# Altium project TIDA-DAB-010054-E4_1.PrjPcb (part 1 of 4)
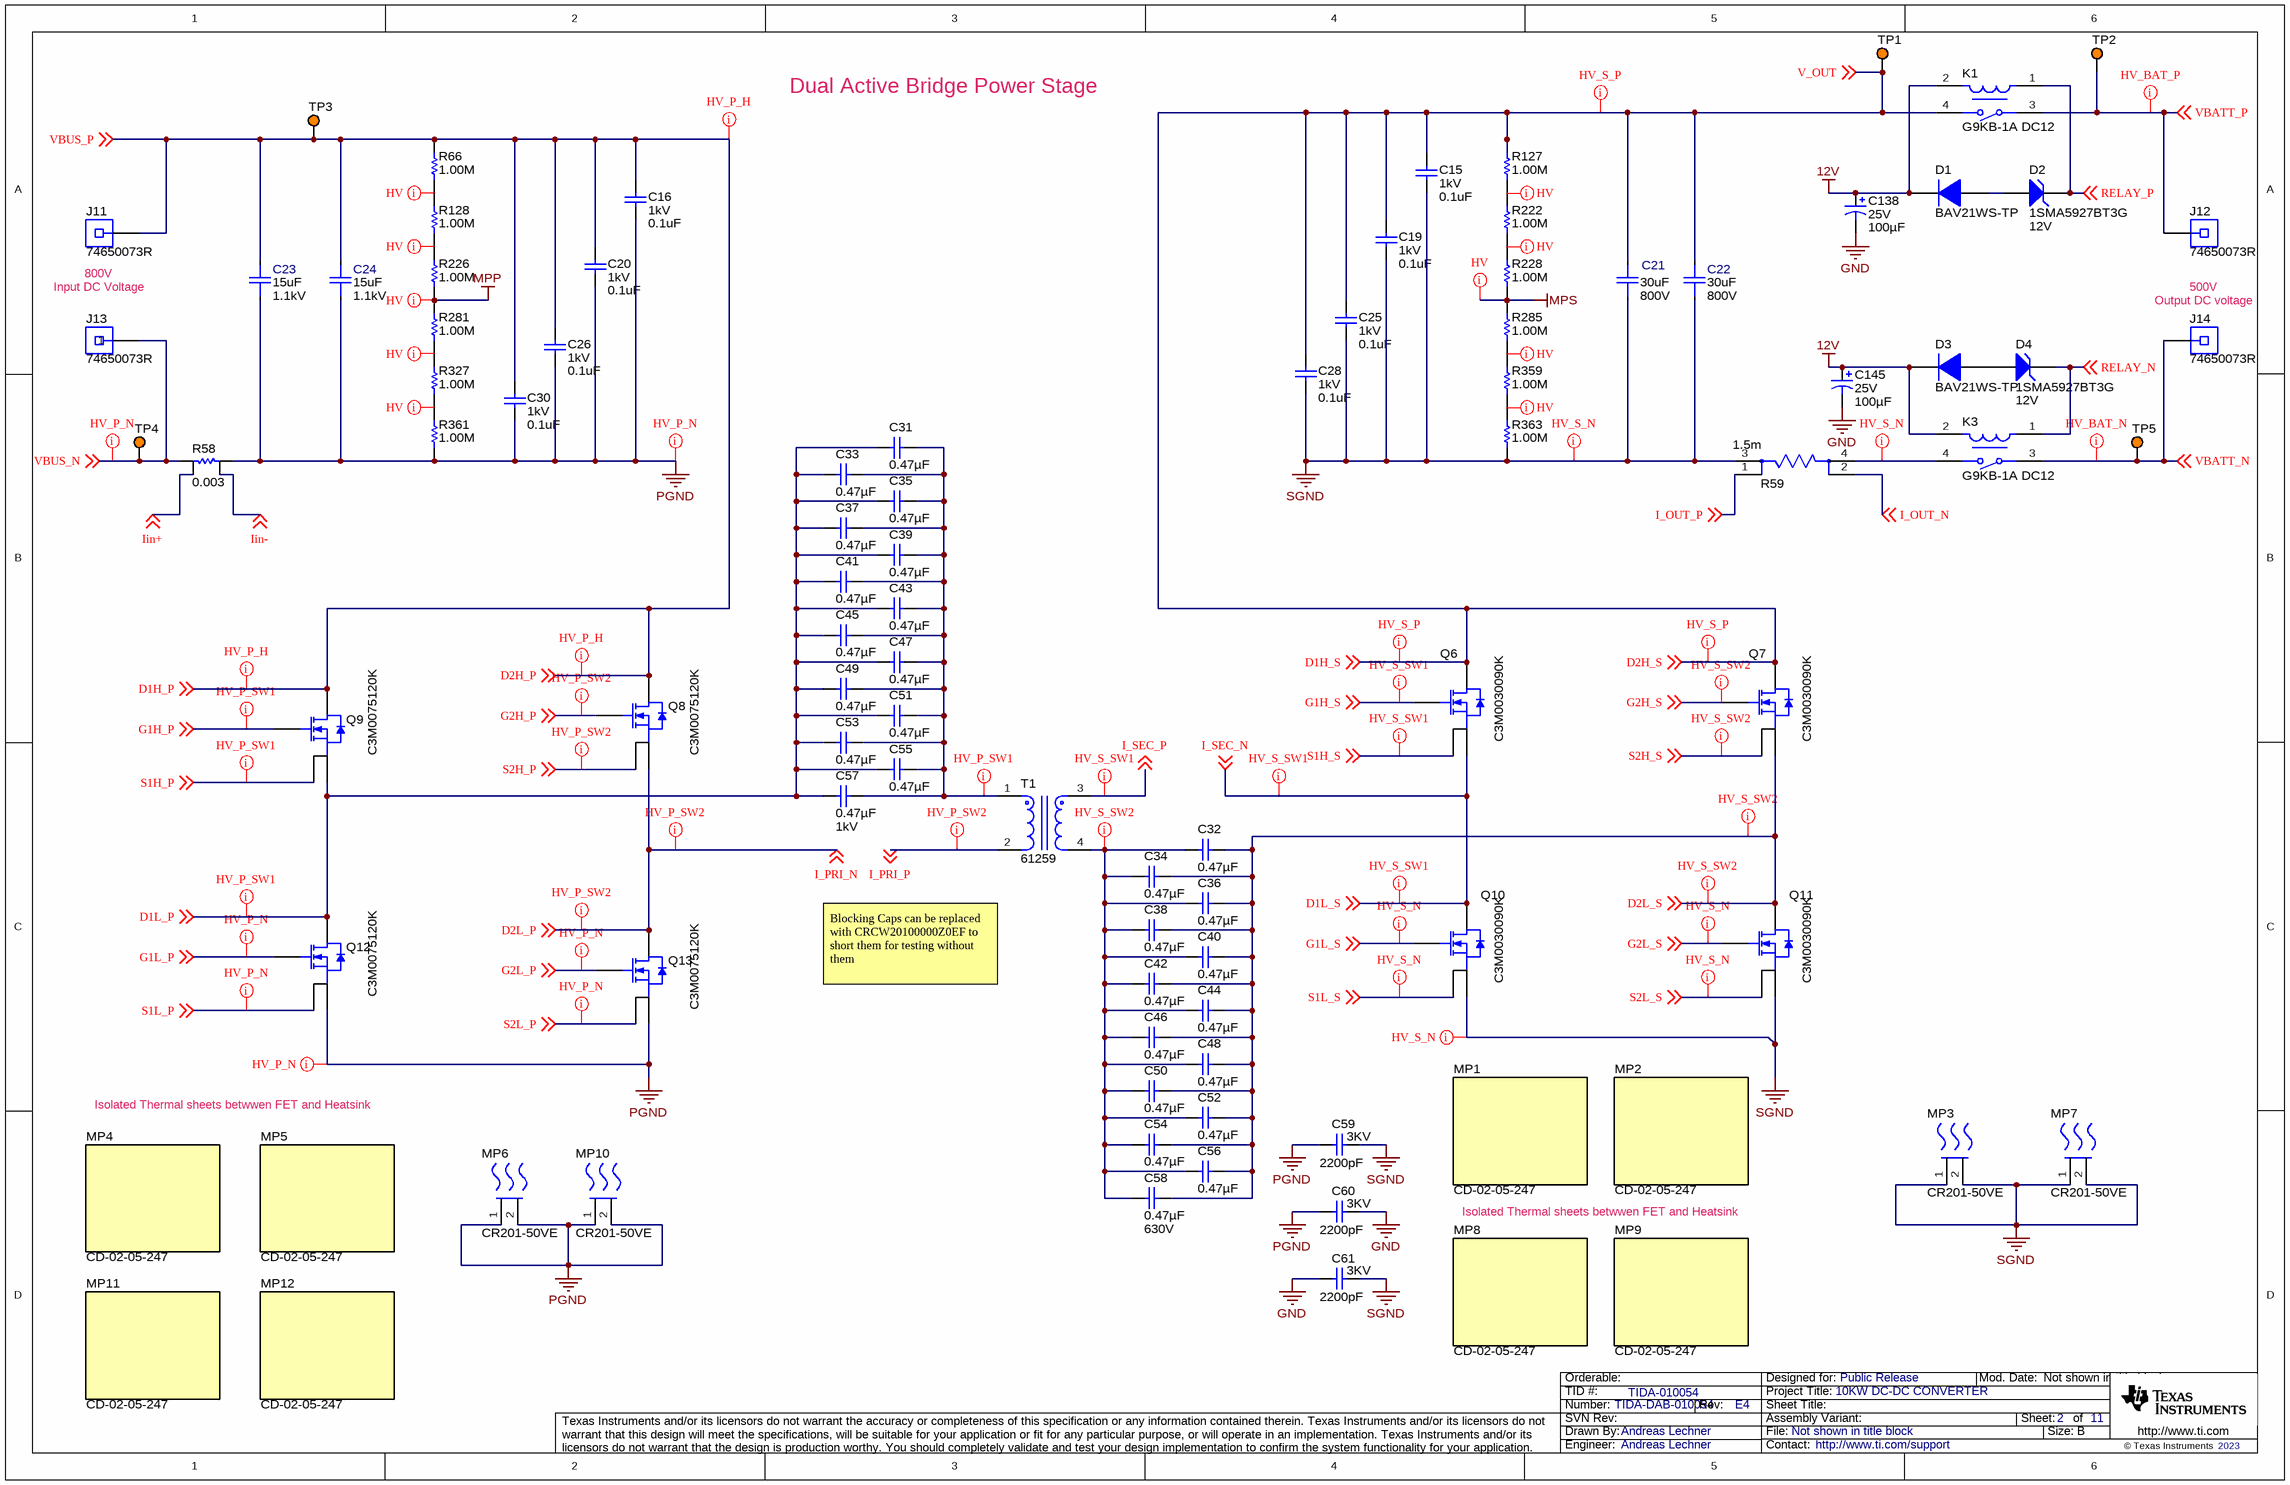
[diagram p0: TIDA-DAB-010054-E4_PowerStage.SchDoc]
CopyrightYear: 2023; DrawnBy: Andreas Lechner; PCB_Layout: Andreas Lechner; PCB_Rev: E4; PRJ_Customer: Public Release; PRJ_Engineer: Andreas Lechner; PRJ_Number: TIDA-DAB-010054; PRJ_Title: 10KW DC-DC CONVERTER; SCH_Rev: E4; TechSupport: http://www.ti.com/support; TID: TIDA-010054
11 sheets, 874 parts. Net scope: global (net labels, ports and power ports of the same name join across sheets).
Board file: TIDA-DAB-010054-E4.PcbDoc
Sheets:
  TIDA-DAB-010054-E4_Block Diagram.SchDoc
  TIDA-DAB-010054-E4_PowerStage.SchDoc
  TIDA-DAB-010054-E4_PrimarySideSensing.SchDoc
  TIDA-DAB-010054-E4_SecondarySideSensing.SchDoc
  TIDA-DAB-010054-E4_GateDriverPrimHB1.SchDoc
  TIDA-DAB-010054-E4_GateDriverPrimHB2.SchDoc
  TIDA-DAB-010054-E4_GateDriverSecHB1.SchDoc
  TIDA-DAB-010054-E4_GateDriverSecHB2.SchDoc
  TIDA-DAB-010054-E4_Power Tree.SchDoc
  TIDA-DAB-010054-E4_Control Card.SchDoc
  TIDA-DAB-010054-E4_EVM_Hardware.SchDoc

## Sheet TIDA-DAB-010054-E4_Block Diagram.SchDoc
size 431 x 279 mm; Date: Not shown in title block; ApprovedBy: Not shown in title block; CheckedBy: Not shown in title block; Author: Not shown in title block; CompanyName: Not shown in title block; Engineer: Not shown in title block; Organization: Not shown in title block; Address1: Not shown in title block; Address2: Not shown in title block; Address3: Not shown in title block; Address4: Not shown in title block; DocumentNumber: 1; Revision: Use project parameter SCH_Rev; SheetNumber: 1; SheetTotal: 11; PageSetup: Record=PageOptions¦CenterHorizontal=True¦CenterVertical=True¦PrintScale=1.00¦XCorrection=1.00¦YCorrection=1.00¦PrintKind=0¦BorderSize=5000000¦LeftOffset=0¦BottomOffset=0¦Orientation=2¦PaperLength=1000¦PaperWidth=1000¦Scale=100¦PaperSource=15¦PrintQuality=600¦MediaType=1¦DitherType=10¦PaperKind=Letter¦PrintScaleMode=1

## Sheet TIDA-DAB-010054-E4_PowerStage.SchDoc
size 431 x 279 mm; Date: Not shown in title block; ApprovedBy: Not shown in title block; CheckedBy: Not shown in title block; Author: Not shown in title block; CompanyName: Not shown in title block; Engineer: Not shown in title block; Organization: Not shown in title block; Address1: Not shown in title block; Address2: Not shown in title block; Address3: Not shown in title block; Address4: Not shown in title block; DocumentNumber: 1; Revision: Use project parameter SCH_Rev; SheetNumber: 2; SheetTotal: 11; PageSetup: Record=PageOptions¦CenterHorizontal=True¦CenterVertical=True¦PrintScale=1.00¦XCorrection=1.00¦YCorrection=1.00¦PrintKind=0¦BorderSize=5000000¦LeftOffset=0¦BottomOffset=0¦Orientation=2¦PaperLength=1000¦PaperWidth=1000¦Scale=100¦PaperSource=15¦PrintQuality=600¦MediaType=1¦DitherType=10¦PaperKind=Letter¦PrintScaleMode=1

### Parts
C15  VDC_V: 1kV  ValueDisplayed: 0.1uF  [1812_254]  (hidden comment: C1812V104KDRACTU)
C16  VDC_V: 1kV  ValueDisplayed: 0.1uF  [1812_254]  (hidden comment: C1812V104KDRACTU)
C19  VDC_V: 1kV  ValueDisplayed: 0.1uF  [1812_254]  (hidden comment: C1812V104KDRACTU)
C20  VDC_V: 1kV  ValueDisplayed: 0.1uF  [1812_254]  (hidden comment: C1812V104KDRACTU)
C21  ValueDisplayed: 30uF  VDC_V: 800V  [FP-B32716H8306K000_RADIAL-MFG]  (hidden comment: B32716H8306K000)
C22  ValueDisplayed: 30uF  VDC_V: 800V  [FP-B32716H8306K000_RADIAL-MFG]  (hidden comment: B32716H8306K000)
C23  ValueDisplayed: 15uF  VDC_V: 1.1kV  [FP-B32716H1156K000_RADIAL-MFG]  (hidden comment: B32716H1156K000)
C24  ValueDisplayed: 15uF  VDC_V: 1.1kV  [FP-B32716H1156K000_RADIAL-MFG]  (hidden comment: B32716H1156K000)
C25  VDC_V: 1kV  ValueDisplayed: 0.1uF  [1812_254]  (hidden comment: C1812V104KDRACTU)
C26  VDC_V: 1kV  ValueDisplayed: 0.1uF  [1812_254]  (hidden comment: C1812V104KDRACTU)
C28  VDC_V: 1kV  ValueDisplayed: 0.1uF  [1812_254]  (hidden comment: C1812V104KDRACTU)
C30  VDC_V: 1kV  ValueDisplayed: 0.1uF  [1812_254]  (hidden comment: C1812V104KDRACTU)
C31  ValueDisplayed: 0.47µF  [2220]  (hidden comment: 2220Y1K00474KETWS2)
C32  ValueDisplayed: 0.47µF  [2220_280]  (hidden comment: CGA9P1X7T2J474M250KC)
C33  ValueDisplayed: 0.47µF  [2220]  (hidden comment: 2220Y1K00474KETWS2)
C34  ValueDisplayed: 0.47µF  [2220_280]  (hidden comment: CGA9P1X7T2J474M250KC)
C35  ValueDisplayed: 0.47µF  [2220]  (hidden comment: 2220Y1K00474KETWS2)
C36  ValueDisplayed: 0.47µF  [2220_280]  (hidden comment: CGA9P1X7T2J474M250KC)
C37  ValueDisplayed: 0.47µF  [2220]  (hidden comment: 2220Y1K00474KETWS2)
C38  ValueDisplayed: 0.47µF  [2220_280]  (hidden comment: CGA9P1X7T2J474M250KC)
C39  ValueDisplayed: 0.47µF  [2220]  (hidden comment: 2220Y1K00474KETWS2)
C40  ValueDisplayed: 0.47µF  [2220_280]  (hidden comment: CGA9P1X7T2J474M250KC)
C41  ValueDisplayed: 0.47µF  [2220]  (hidden comment: 2220Y1K00474KETWS2)
C42  ValueDisplayed: 0.47µF  [2220_280]  (hidden comment: CGA9P1X7T2J474M250KC)
C43  ValueDisplayed: 0.47µF  [2220]  (hidden comment: 2220Y1K00474KETWS2)
C44  ValueDisplayed: 0.47µF  [2220_280]  (hidden comment: CGA9P1X7T2J474M250KC)
C45  ValueDisplayed: 0.47µF  [2220]  (hidden comment: 2220Y1K00474KETWS2)
C46  ValueDisplayed: 0.47µF  [2220_280]  (hidden comment: CGA9P1X7T2J474M250KC)
C47  ValueDisplayed: 0.47µF  [2220]  (hidden comment: 2220Y1K00474KETWS2)
C48  ValueDisplayed: 0.47µF  [2220_280]  (hidden comment: CGA9P1X7T2J474M250KC)
C49  ValueDisplayed: 0.47µF  [2220]  (hidden comment: 2220Y1K00474KETWS2)
C50  ValueDisplayed: 0.47µF  [2220_280]  (hidden comment: CGA9P1X7T2J474M250KC)
C51  ValueDisplayed: 0.47µF  [2220]  (hidden comment: 2220Y1K00474KETWS2)
C52  ValueDisplayed: 0.47µF  [2220_280]  (hidden comment: CGA9P1X7T2J474M250KC)
C53  ValueDisplayed: 0.47µF  [2220]  (hidden comment: 2220Y1K00474KETWS2)
C54  ValueDisplayed: 0.47µF  [2220_280]  (hidden comment: CGA9P1X7T2J474M250KC)
C55  ValueDisplayed: 0.47µF  [2220]  (hidden comment: 2220Y1K00474KETWS2)
C56  ValueDisplayed: 0.47µF  [2220_280]  (hidden comment: CGA9P1X7T2J474M250KC)
C57  ValueDisplayed: 0.47µF  VDC_V: 1kV  [2220]  (hidden comment: 2220Y1K00474KETWS2)
C58  ValueDisplayed: 0.47µF  VDC_V: 630V  [2220_280]  (hidden comment: CGA9P1X7T2J474M250KC)
C59  VDC_V: 3KV  ValueDisplayed: 2200pF  [CAPRD1000W60D900H1200]  (hidden comment: CK45-B3FD222KYVNA)
C60  VDC_V: 3KV  ValueDisplayed: 2200pF  [CAPRD1000W60D900H1200]  (hidden comment: CK45-B3FD222KYVNA)
C61  VDC_V: 3KV  ValueDisplayed: 2200pF  [CAPRD1000W60D900H1200]  (hidden comment: CK45-B3FD222KYVNA)
C138  VDC_V: 25V  ValueDisplayed: 100µF  [UWT_630x770]  (hidden comment: UWT1E101MCL1GS)
C145  VDC_V: 25V  ValueDisplayed: 100µF  [UWT_630x770]  (hidden comment: UWT1E101MCL1GS)
D1  BAV21WS-TP  [SOD-323]
D2  1SMA5927BT3G  value 12V  [SMA]
D3  BAV21WS-TP  [SOD-323]
D4  1SMA5927BT3G  value 12V  [SMA]
J11  74650073R  [Wurth_WP-THRBU]
J12  74650073R  [Wurth_WP-THRBU]
J13  74650073R  [Wurth_WP-THRBU]
J14  74650073R  [Wurth_WP-THRBU]
K1  G9KB-1A DC12  [FP-G9KB-1A DC12_PTH_RELAY_50MM0_36MM7-MFG]
K3  G9KB-1A DC12  [FP-G9KB-1A DC12_PTH_RELAY_50MM0_36MM7-MFG]
MP1  CD-02-05-247  [FP-CD-02-05-247_THERM_PAD_24MM13_19MM05-MFG]
MP2  CD-02-05-247  [FP-CD-02-05-247_THERM_PAD_24MM13_19MM05-MFG]
MP3  CR201-50VE  [FP-CR201-50VE_PTH_HEATSINKS_34MM0_50MM0-MFG]
MP4  CD-02-05-247  [FP-CD-02-05-247_THERM_PAD_24MM13_19MM05-MFG]
MP5  CD-02-05-247  [FP-CD-02-05-247_THERM_PAD_24MM13_19MM05-MFG]
MP6  CR201-50VE  [FP-CR201-50VE_PTH_HEATSINKS_34MM0_50MM0-MFG]
MP7  CR201-50VE  [FP-CR201-50VE_PTH_HEATSINKS_34MM0_50MM0-MFG]
MP8  CD-02-05-247  [FP-CD-02-05-247_THERM_PAD_24MM13_19MM05-MFG]
MP9  CD-02-05-247  [FP-CD-02-05-247_THERM_PAD_24MM13_19MM05-MFG]
MP10  CR201-50VE  [FP-CR201-50VE_PTH_HEATSINKS_34MM0_50MM0-MFG]
MP11  CD-02-05-247  [FP-CD-02-05-247_THERM_PAD_24MM13_19MM05-MFG]
MP12  CD-02-05-247  [FP-CD-02-05-247_THERM_PAD_24MM13_19MM05-MFG]
Q6  C3M0030090K  [TO-247-4]
Q7  C3M0030090K  [TO-247-4]
Q8  C3M0075120K  [TO-247-4]
Q9  C3M0075120K  [TO-247-4]
Q10  C3M0030090K  [TO-247-4]
Q11  C3M0030090K  [TO-247-4]
Q12  C3M0075120K  [TO-247-4]
Q13  C3M0075120K  [TO-247-4]
R58  ValueDisplayed: 0.003  [WSL3637_0_002]  (hidden comment: WSL36373L000FEA)
R59  value 1.5m  [FP-WSL36371L500FEA_3637-MFG]  (hidden comment: WSL36371L500FEA)
R66  ValueDisplayed: 1.00M  [1206]  (hidden comment: CRCW12061M00FKEA)
R127  ValueDisplayed: 1.00M  [1206]  (hidden comment: CRCW12061M00FKEA)
R128  ValueDisplayed: 1.00M  [1206]  (hidden comment: CRCW12061M00FKEA)
R222  ValueDisplayed: 1.00M  [1206]  (hidden comment: CRCW12061M00FKEA)
R226  ValueDisplayed: 1.00M  [1206]  (hidden comment: CRCW12061M00FKEA)
R228  ValueDisplayed: 1.00M  [1206]  (hidden comment: CRCW12061M00FKEA)
R281  ValueDisplayed: 1.00M  [1206]  (hidden comment: CRCW12061M00FKEA)
R285  ValueDisplayed: 1.00M  [1206]  (hidden comment: CRCW12061M00FKEA)
R327  ValueDisplayed: 1.00M  [1206]  (hidden comment: CRCW12061M00FKEA)
R359  ValueDisplayed: 1.00M  [1206]  (hidden comment: CRCW12061M00FKEA)
R361  ValueDisplayed: 1.00M  [1206]  (hidden comment: CRCW12061M00FKEA)
R363  ValueDisplayed: 1.00M  [1206]  (hidden comment: CRCW12061M00FKEA)
T1  61259  [FP-61259_PTH_XFRMR_130MM0_90MM0-MFG]
TP1  5003  [Keystone5003]  (value not drawn)
TP2  5003  [Keystone5003]  (value not drawn)
TP3  5003  [Keystone5003]  (value not drawn)
TP4  5003  [Keystone5003]  (value not drawn)
TP5  5003  [Keystone5003]  (value not drawn)

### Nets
12V: C138.1(+) C145.1(+) D1.1(K) D3.1(K) K1.2 K3.2
GND: C60.1 C61.2 C138.2(-) C145.2(-)
MPP: R226.1 R281.2
MPS: R228.1 R285.2
PGND: C16.2 C20.2 C23.1 C24.1 C26.2 C30.2 C59.2 C60.2 MP6.1(MNT_1) MP6.2(MNT_2) MP10.1(MNT_1) MP10.2(MNT_2) Q12.2(S) Q13.2(S) R58.2 R361.1
S1H_P: Q9.3(KS) ; off-sheet S1H_P  [project net GND_TOP1]
S1H_S: Q6.3(KS) ; off-sheet S1H_S  [project net GND_TOP3]
S1L_P: Q12.3(KS) ; off-sheet S1L_P  [project net GND_BOT1]
S1L_S: Q10.3(KS) ; off-sheet S1L_S  [project net GND_BOT3]
S2H_P: Q8.3(KS) ; off-sheet S2H_P  [project net GND_TOP2]
S2H_S: Q7.3(KS) ; off-sheet S2H_S  [project net GND_TOP4]
S2L_P: Q13.3(KS) ; off-sheet S2L_P  [project net GND_BOT2]
S2L_S: Q11.3(KS) ; off-sheet S2L_S  [project net GND_BOT4]
SGND: C15.2 C19.2 C21.1 C22.1 C25.2 C28.2 C59.1 C61.1 MP3.1(MNT_1) MP3.2(MNT_2) MP7.1(MNT_1) MP7.2(MNT_2) Q10.2(S) Q11.2(S) R59.3(I1) R363.1
D1H_P: C16.1 C20.1 C23.2 C24.2 C26.1 C30.1 J11.1 Q8.1(D) Q9.1(D) R66.2 TP3.1 ; off-sheet VBUS_P, off-sheet D1H_P, off-sheet D2H_P  [also labelled D2H_P, VBUS_P]
D1H_S: C15.1 C19.1 C21.2 C22.2 C25.1 C28.1 K1.4 Q6.1(D) Q7.1(D) R127.2 TP1.1 ; off-sheet D1H_S, off-sheet D2H_S, off-sheet V_OUT  [also labelled D2H_S, V_OUT]
D1L_P: C31.2 C33.2 C35.2 C37.2 C39.2 C41.2 C43.2 C45.2 C47.2 C49.2 C51.2 C53.2 C55.2 C57.2 Q9.2(S) Q12.1(D) ; off-sheet D1L_P
D1L_S: Q6.2(S) Q10.1(D) ; off-sheet D1L_S, off-sheet I_SEC_N  [also labelled I_SEC_N]
D2L_P: Q8.2(S) Q13.1(D) ; off-sheet D2L_P, off-sheet I_PRI_N  [also labelled I_PRI_N]
D2L_S: C32.1 C34.1 C36.1 C38.1 C40.1 C42.1 C44.1 C46.1 C48.1 C50.1 C52.1 C54.1 C56.1 C58.1 Q7.2(S) Q11.1(D) ; off-sheet D2L_S
G1H_P: Q9.4(G) ; off-sheet G1H_P
G1H_S: Q6.4(G) ; off-sheet G1H_S
G1L_P: Q12.4(G) ; off-sheet G1L_P
G1L_S: Q10.4(G) ; off-sheet G1L_S
G2H_P: Q8.4(G) ; off-sheet G2H_P
G2H_S: Q7.4(G) ; off-sheet G2H_S
G2L_P: Q13.4(G) ; off-sheet G2L_P
G2L_S: Q11.4(G) ; off-sheet G2L_S
I_OUT_N: R59.2(E2) ; off-sheet I_OUT_N
I_OUT_P: R59.1(E1) ; off-sheet I_OUT_P
I_PRI_P: T1.2 ; off-sheet I_PRI_P
I_SEC_P: T1.3 ; off-sheet I_SEC_P
Iin+: R58.3 ; off-sheet Iin+
Iin-: R58.4 ; off-sheet Iin-
RELAY_N: D4.1(K) K3.1 ; off-sheet RELAY_N
RELAY_P: D2.1(K) K1.1 ; off-sheet RELAY_P
VBATT_N: J14.1 K3.3 TP5.1 ; off-sheet VBATT_N
VBATT_P: J12.1 K1.3 TP2.1 ; off-sheet VBATT_P
VBUS_N: J13.1 R58.1 TP4.1 ; off-sheet VBUS_N
NetC31_1: C31.1 C33.1 C35.1 C37.1 C39.1 C41.1 C43.1 C45.1 C47.1 C49.1 C51.1 C53.1 C55.1 C57.1 T1.1
NetC32_2: C32.2 C34.2 C36.2 C38.2 C40.2 C42.2 C44.2 C46.2 C48.2 C50.2 C52.2 C54.2 C56.2 C58.2 T1.4
NetD1_2: D1.2(A) D2.2(A)
NetD3_2: D3.2(A) D4.2(A)
NetK3_4: K3.4 R59.4(I2)
NetR66_1: R66.1 R128.2
NetR127_1: R127.1 R222.2
NetR128_1: R128.1 R226.2
NetR222_1: R222.1 R228.2
NetR281_1: R281.1 R327.2
NetR285_1: R285.1 R359.2
NetR327_1: R327.1 R361.2
NetR359_1: R359.1 R363.2

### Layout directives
net class HV_P_H: D1H_P
net class HV_S_P: D1H_S
net class HV_S_SW1: D1L_S, G1H_S, GND_TOP3, I_SEC_P
net class HV_S_SW2: D2L_S, G2H_S, GND_TOP4, NetC32_2
net class HV_P_N: G1L_P, G2L_P, GND_BOT1, GND_BOT2, PGND, VBUS_N
net class HV_S_N: G1L_S, G2L_S, GND_BOT3, GND_BOT4, NetK3_4, SGND
net class HV_P_SW1: D1L_P, G1H_P, GND_TOP1, NetC31_1
net class HV_P_SW2: D2L_P, G2H_P, GND_TOP2, I_PRI_P
net class HV: MPP, MPS, NetR66_1, NetR127_1, NetR128_1, NetR222_1, NetR281_1, NetR285_1, NetR327_1, NetR359_1
net class HV_BAT_N: VBATT_N
net class HV_BAT_P: VBATT_P

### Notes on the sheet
- Dual Active Bridge Power Stage
- Input DC Voltage
- (near J11) 800V
- (near J14) Output DC voltage
- 500V
- Blocking Caps can be replaced with CRCW20100000Z0EF to short them for testing without them
- Isolated Thermal sheets betwwen FET and Heatsink

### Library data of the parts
C15 C16 C19 C20 C25 C26 C28 C30 = CMP-0009324-2: CAP, CERM, 0.1 uF, 1000 V, +/- 10%, X7R, 1812; Manufacturer: Kemet; TaMin_C: -55°C; Polarized: N; SizeAreaWB_mm2: 23.1; Value1: Unknown; U/M: EA; Value: 0.1uF; TaMax_C: 125°C; SizeZ_mm: 2.54; SizeX_mm: 4.5; SizeY_mm: 3.2; Cap_Case: 1812; Value2: 1000V; SizeArea_mm2: 14.4; Cap_F: 100nF; AEC Category: Q200
C21 C22 = CMP-0120640-1: 30 µF Film Capacitor 800V Polypropylene (PP), Metallized Radial - 4 Leads; Manufacturer: TDK; AEC Grade: Grade 2; AEC Qualified: Yes; Cap_F: 30µF; SizeZ_mm: 45mm; Tolerance_%: 10%; Value: 30µF
C23 C24 = CMP-0120639-1: Power Film Capacitor, 15 uF, 1.1 kVDC, ± 10%, Metallized PP, Radial Box - 4 Pin, Through Hole; Manufacturer: TDK; AEC Grade: Grade 2; AEC Qualified: Yes; Cap_F: 15µF; SizeZ_mm: 45mm; Value: 15µF
C31 C33 C35 C37 C39 C41 C43 C45 C47 C49 C51 C53 C55 = CMP-0086177-1: CAP, CERM, 0.47 µF, 1000 V,+/- 10%, X7R, AEC-Q200 Grade 1, 2220; Manufacturer: Knowles Capacitors; SizeAreaWB_mm2: 53.9; AEC Category: Q200; TaMax_C: 125°C; SizeArea_mm2: 28.5; SizeX_mm: 5.7; SizeZ_mm: 1.35; Value: 0.47uF; AEC Qualified: Y; TaMin_C: -55°C; SizeY_mm: 5; Value2: 1000V; AEC Grade: 1; U/M: EA; Cap_F: 470nF; Polarized: N; VDC_V: 1kV
C32 C34 C36 C38 C40 C42 C44 C46 C48 C50 C52 C54 C56 = CMP-0860865-1: CAP, CERM, 0.47 µF, 630 V,+/- 20%, X7T, AEC-Q200 Grade 1, 2220; Manufacturer: TDK; SizeZ_mm: 2.8; Value2: 630V; SizeY_mm: 5; AEC Qualified: Y; Cap_Case: 2220; Polarized: N; SizeArea_mm2: 28.5; U/M: EA; AEC Grade: 1; AEC Category: Q200; TaMax_C: 125°C; TaMin_C: -55°C; Cap_F: 470nF; SizeAreaWB_mm2: 53.9; SizeX_mm: 5.7; Value: 0.47uF
C57 = CMP-0086177-1: CAP, CERM, 0.47 µF, 1000 V,+/- 10%, X7R, AEC-Q200 Grade 1, 2220; Manufacturer: Knowles Capacitors; SizeAreaWB_mm2: 53.9; AEC Category: Q200; TaMax_C: 125°C; SizeArea_mm2: 28.5; SizeX_mm: 5.7; SizeZ_mm: 1.35; Value: 0.47uF; AEC Qualified: Y; TaMin_C: -55°C; SizeY_mm: 5; Value2: 1000V; AEC Grade: 1; U/M: EA; Cap_F: 470nF; Polarized: N
C58 = CMP-0860865-1: CAP, CERM, 0.47 µF, 630 V,+/- 20%, X7T, AEC-Q200 Grade 1, 2220; Manufacturer: TDK; SizeZ_mm: 2.8; SizeY_mm: 5; AEC Qualified: Y; Cap_Case: 2220; Polarized: N; SizeArea_mm2: 28.5; U/M: EA; AEC Grade: 1; AEC Category: Q200; TaMax_C: 125°C; TaMin_C: -55°C; Cap_F: 470nF; SizeAreaWB_mm2: 53.9; SizeX_mm: 5.7; Value: 0.47uF
C59-C61 = CMP-0009601-2: CAP, CERM, 2200 pF, 3KV, +/- 20%, E, Cap, 7x12x9 mm; Manufacturer: MuRata; TaMin_C: -25°C; Polarized: N; SizeAreaWB_mm2: 121.5; Value1: Unknown; U/M: EA; Value: 2200pF; TaMax_C: 85°C; SizeZ_mm: 12.5; SizeX_mm: 11.5; SizeY_mm: 7; Value2: 250V; SizeArea_mm2: 80.5; CompType: Capacitor; Cap_F: 2.2nF; AEC Category: Q200
C138 C145 = CMP-0081462-1: CAP, AL, 100 µF, 25 V, +/- 20%, SMD; Manufacturer: Nichicon; TaMin_C: -55°C; Polarized: Y; SizeAreaWB_mm2: 77.4; U/M: EA; Value: 100uF; TaMax_C: 105°C; SizeZ_mm: 8; SizeX_mm: 7; SizeY_mm: 6.6; Cap_Case: 6.3x7.7mm; SizeArea_mm2: 46.2; CompType: Capacitor; AEC Qualified: N; IRMS_A: 91mA; AEC Category: Q200
D1 D3 = CMP-0077069-2: Diode, Standard Recovery Rectifier, 250 V, 0.2 A, SOD-323; Manufacturer: Micro Commercial Components; TJmax_C: 150°C; AEC Category: Q101; Green_Lifecycle: Not Set; Value: 250V; Vf_V: 1.25V; SizeZ_mm: 1.0; Value1: 0.2A; SizeX_mm: 2.7; SizeAreaWB_mm2: 8.695; SizeArea_mm2: 3.645; AEC Qualified: N; Io_A: 200mA; SizeY_mm: 1.35; Green_REACh: Incomplete
D2 D4 = CMP-0005523-4: Diode, Zener, 12 V, 1.5 W, SMA; Manufacturer: ON Semiconductor; SizeArea_mm2: 16.3228; Value1: 1.5W; SizeAreaWB_mm2: 37.3428; SizeX_mm: 5.59; SizeZ_mm: 2.87; SizeY_mm: 2.92; AEC Category: Q101; RJA_CperW: 250
J11-J14 = CMP-0078526-1: Power Element Bush, M3, TH; Manufacturer: Wurth Elektronik; Gender: Female; Current_A: 50A; ContactFinish: Tin; CompType: Screw Terminal
K1 K3 = CMP-0049812-1: General Purpose Relay SPST-NO (1 Form A) 12VDC Coil Through Hole; Manufacturer: Omron; Coil Current_A: 235.3mA; Coil Power_W: 2.8W; Coil Type: Non-Latching; Coil Voltage_VDC: 12V; Contact Rating_A: 50A; SizeZ_mm: 50.5mm; AEC Qualified: No; Coil Resistance: 51Ω; TaMax_C: +85°C; TaMin_C: -40°C
MP1 MP2 MP4 MP5 MP8 MP9 MP11 MP12 = CMP-0098314-1: CD-02-05 Series 0.95 x 0.75 inch w/ Hole TO-247 Phase Change Thermal Pad; Manufacturer: Wakefield-Vette; AEC Qualified: No; SizeZ_mm: 0.0033inch
MP3 MP6 MP7 MP10 = CMP-0091185-1: Heat Sinks Aluminum heatsink 50mmdegreased; Manufacturer: Ohmite; AEC Qualified: No; Natural Thermal Resistance: 3.3°C/W; SizeZ_mm: 75mm; Mating Package: TO-247/TO-264
Q6 Q7 Q10 Q11 = CMP-0084898-1: MOSFET, N-CH, 900 V, 63 A, TO-247-4; Manufacturer: Cree; Alternate Manufacturer: None; ChMode: Enhancement; AEC Category: Q101; AEC Qualified: N; Value2: 87 nC; SizeY_mm: 5.02; SizeZ_mm: 27.97; QgTyp_nC: 87; SizeArea_mm2: 80.0188; SizeAreaWB_mm2: 125.9388; SizeX_mm: 15.94; IdsMax_A: 63A; VdsMax_V: 900V; Vgs_V: 15V; Value1: ? ohm; Value: 900V
Q8 Q9 Q12 Q13 = CMP-0085490-1: MOSFET, N-CH, 1200 V, 30 A, TO-247-4; Alternate Manufacturer: None; Manufacturer: Cree; VdsMax_V: 1.2kV; ChMode: Enhancement; SizeX_mm: 15.94; SizeY_mm: 5.02; Value2: 51 nC; AEC Qualified: N; Value: 1200V; Value1: ? ohm; QgTyp_nC: 51; IdsMax_A: 30A; AEC Category: Q101; SizeArea_mm2: 80.0188; SizeZ_mm: 27.97; Vgs_V: 19V; SizeAreaWB_mm2: 125.9388
R58 = CMP-0082607-1: RES, 0.003, 1%, 3 W, AEC-Q200 Grade 0, 9.14x9.4mm; Manufacturer: Vishay-Dale; Value_Code: 3L000; SizeAreaWB_mm2: 126.996; SizeArea_mm2: 85.916; AEC Qualified: Y; AEC Category: Q200; Res_ohm: 3m; Value: 0.003; SizeZ_mm: 0.889; EIA_Code: E96; TempCo: 50 ppm/C; AEC Grade: 0; Power_W: 3W; SizeY_mm: 9.4; CompType: Resistor; SizeX_mm: 9.14
R59 = CMP-0091524-1: 1.5 mOhms ±1% 3W Chip Resistor Nonstandard Anti-Sulfur, Automotive AEC-Q200, Current Sense, Moisture Resistant, Pulse Withstanding Metal Element; Manufacturer: Vishay; TempCo: 75ppm/°C; AEC Qualified: Yes; AEC Grade: Grade 0; SizeZ_mm: 0.889mm
R66 R127 R128 R222 R226 R228 R281 R285 R327 R359 R361 R363 = CMP-0016716-3: RES, 1.00 M, 1%, 0.25 W, AEC-Q200 Grade 0, 1206; Manufacturer: Vishay-Dale; Power_W: 250mW; TempCo: 100 ppm/C; Value_Code: 1M00; Value: 1.00Meg; EIA_Code: E96; Res_ohm: 1M; SizeX_mm: 3.2; SizeY_mm: 1.6; SizeZ_mm: 1.35; Value2: 0.25W; SizeArea_mm2: 5.12; AEC Qualified: Y; VDC_V: 200V; AEC Category: Q200; AEC Grade: 0
T1 = CMP-0091486-2: 10kW SMPS Transformer, 24:15, 100kHz, 5000VDC Dielectric, 130x90x52mm; Manufacturer: Payton Planar; TaMin_C: -40°C; TaMax_C: +125°C; Ind_H: 15.3µH; Frequency_Fixed: 100-200kHz; AEC Qualified: No; SizeZ_mm: 52mm
TP1-TP5 = CMP-0055140-1: Test Point, Miniature, Orange, TH; Manufacturer: Keystone; CNHeader: FALSE; Green_Lifecycle: Active; Green_REACh: Passed; ContactFinish: Silver; CT: TRUE

## Sheet TIDA-DAB-010054-E4_PrimarySideSensing.SchDoc
size 431 x 279 mm; Date: Not shown in title block; ApprovedBy: Not shown in title block; CheckedBy: Not shown in title block; Author: Not shown in title block; CompanyName: Not shown in title block; Engineer: Not shown in title block; Organization: Not shown in title block; Address1: Not shown in title block; Address2: Not shown in title block; Address3: Not shown in title block; Address4: Not shown in title block; DocumentNumber: 1; Revision: Use project parameter SCH_Rev; SheetNumber: 3; SheetTotal: 11; PageSetup: Record=PageOptions¦CenterHorizontal=True¦CenterVertical=True¦PrintScale=1.00¦XCorrection=1.00¦YCorrection=1.00¦PrintKind=0¦BorderSize=5000000¦LeftOffset=0¦BottomOffset=0¦Orientation=2¦PaperLength=1000¦PaperWidth=1000¦Scale=100¦PaperSource=15¦PrintQuality=600¦MediaType=1¦DitherType=10¦PaperKind=Letter¦PrintScaleMode=1
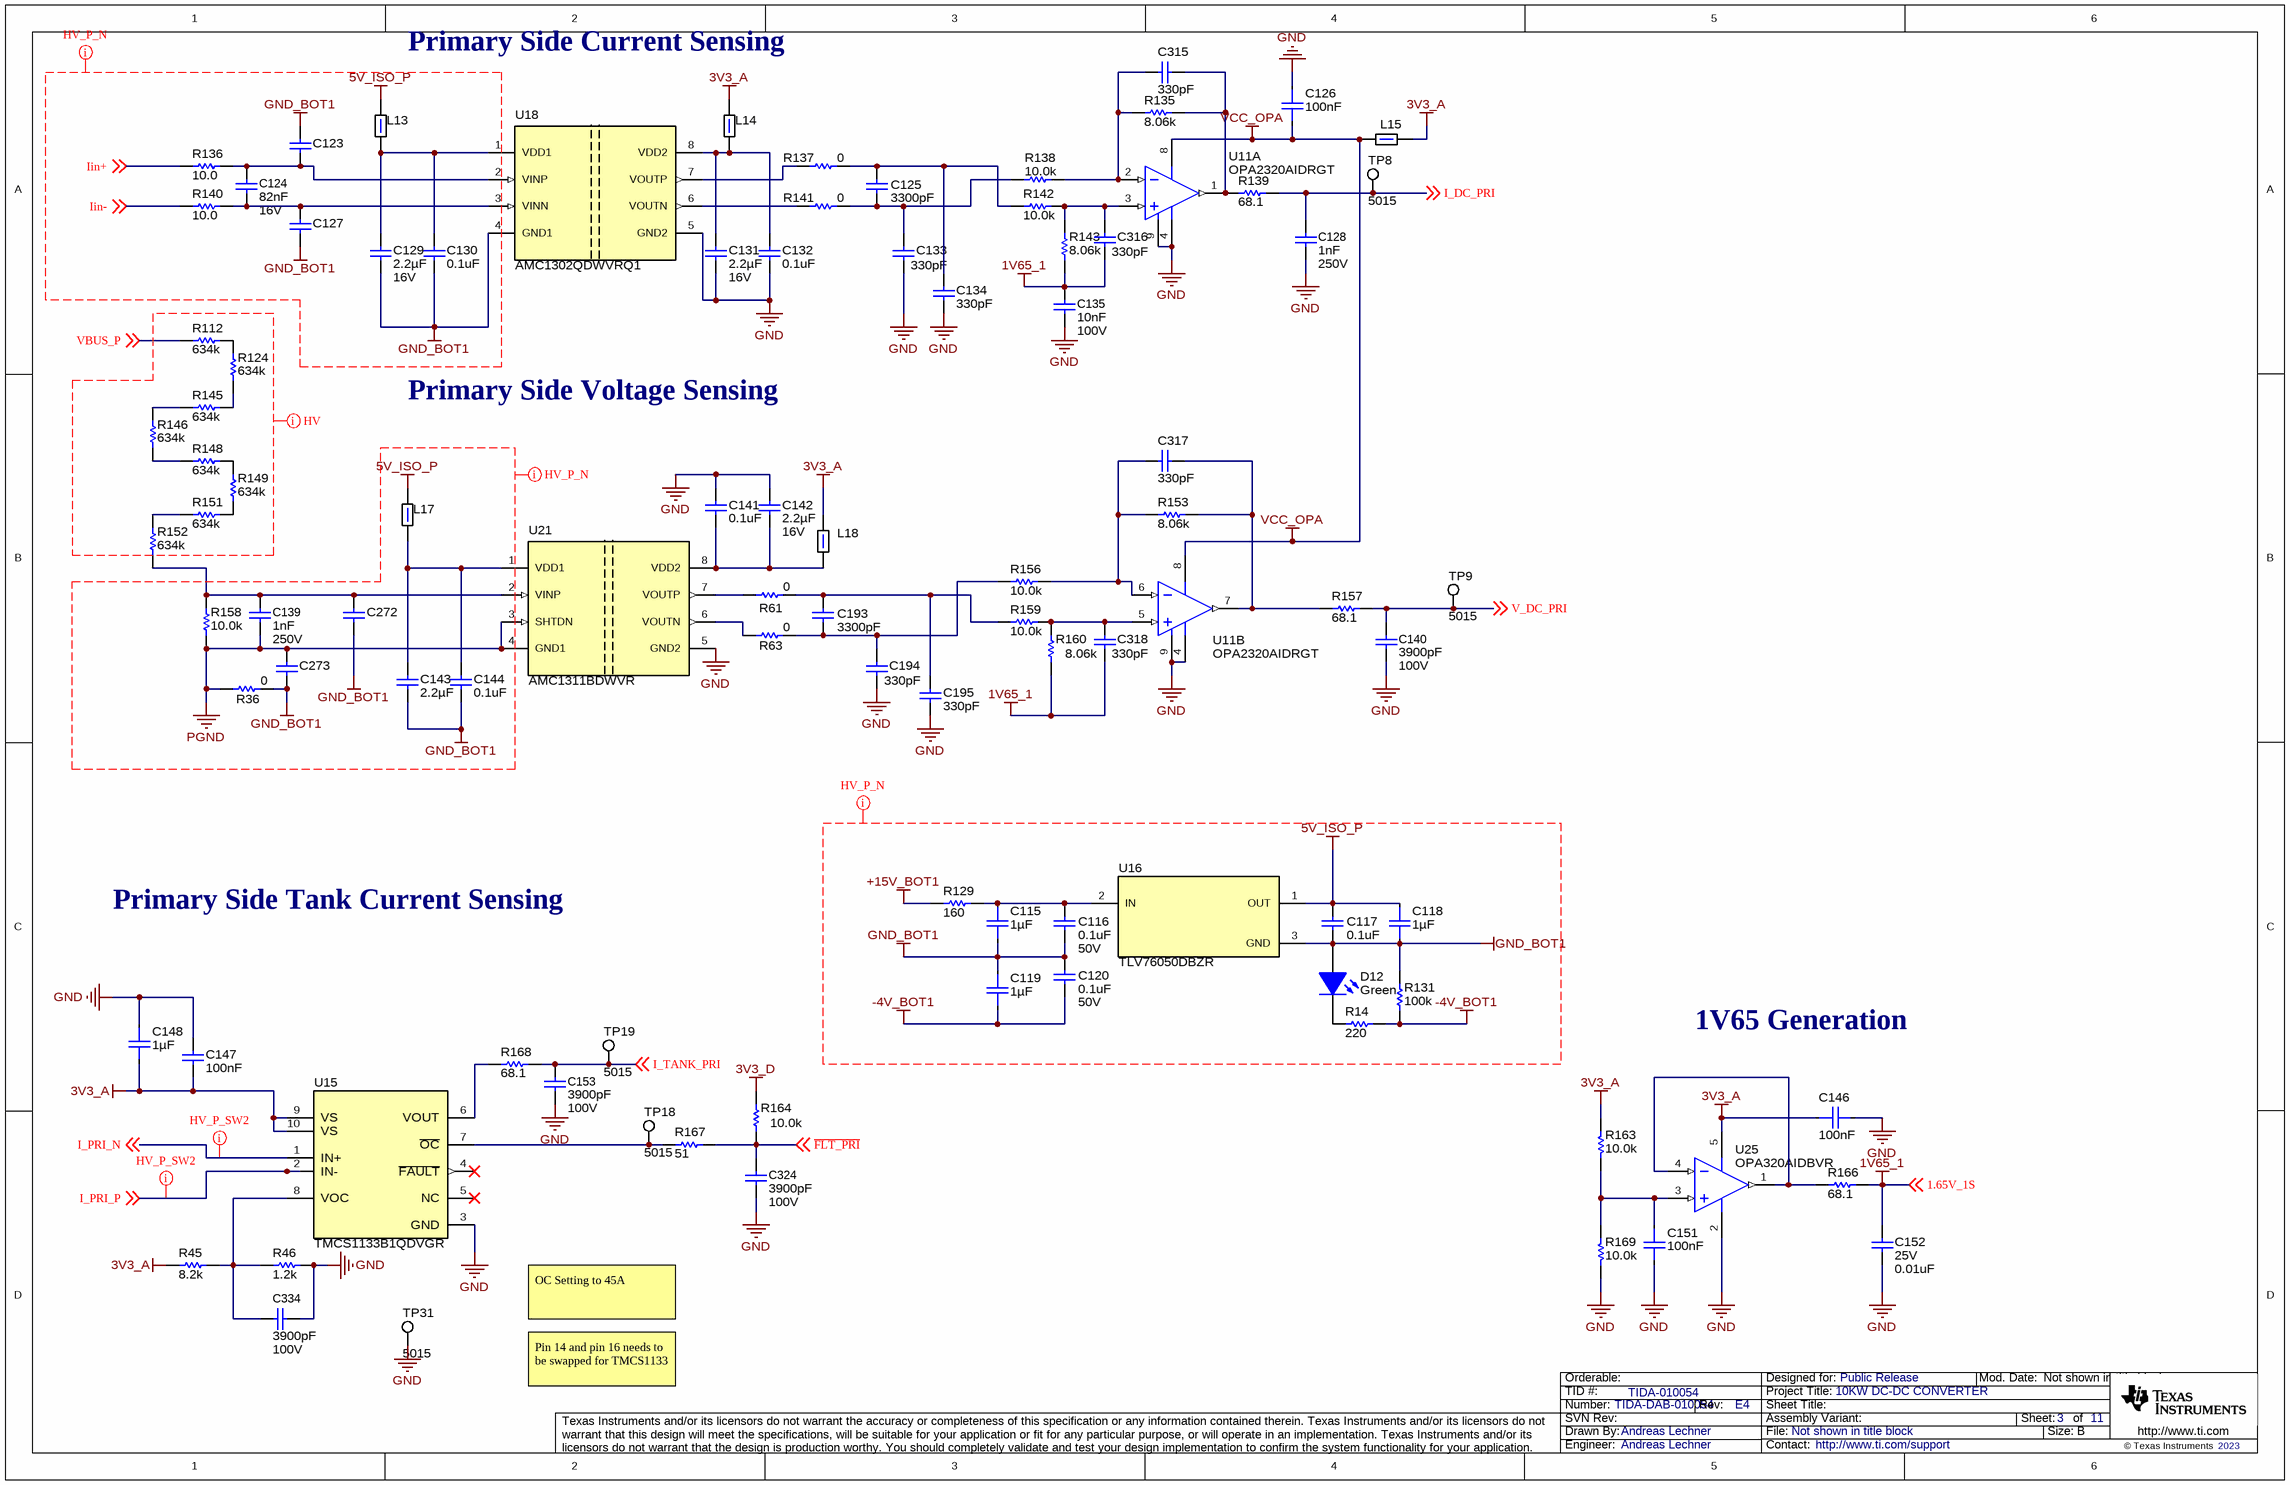
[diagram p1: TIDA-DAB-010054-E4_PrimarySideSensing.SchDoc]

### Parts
C115  Cap_F: 1µF  [FP-CL10B105KA8VPJC_0603-MFG]  (hidden comment: CL10B105KA8VPJC)
C116  VDC_V: 50V  ValueDisplayed: 0.1uF  [0402L]  (hidden comment: GCM155R71H104KE02D)
C117  ValueDisplayed: 0.1uF  [0402L]  (hidden comment: GCM155R71H104KE02D)
C118  Cap_F: 1µF  [FP-CL10B105KA8VPJC_0603-MFG]  (hidden comment: CL10B105KA8VPJC)
C119  Cap_F: 1µF  [FP-CL10B105KA8VPJC_0603-MFG]  (hidden comment: CL10B105KA8VPJC)
C120  VDC_V: 50V  ValueDisplayed: 0.1uF  [0402L]  (hidden comment: GCM155R71H104KE02D)
C123  0603ZC100KAT2A  [0603]  (value not drawn)
C124  Cap_F: 82nF  VDC_V: 16V  [0603]  (hidden comment: 0603YC823KAT2A)
C125  ValueDisplayed: 3300pF  [0603]  (hidden comment: GRM1885C1H332JA01D)
C126  Cap_F: 100nF  [FP-CL10B104KA8VPJC_0603-MFG]  (hidden comment: CL10B104KA8VPJC)
C127  0603ZC100KAT2A  [0603]  (value not drawn)
C128  Cap_F: 1nF  VDC_V: 250V  [0603]  (hidden comment: GRM188R72E102KW07D)
C129  Cap_F: 2.2µF  VDC_V: 16V  [0603]  (hidden comment: CC0603KRX7R7BB225)
C130  ValueDisplayed: 0.1uF  [0603]  (hidden comment: CGA3E2X7R1E104K080AA)
C131  Cap_F: 2.2µF  VDC_V: 16V  [0603]  (hidden comment: CC0603KRX7R7BB225)
C132  ValueDisplayed: 0.1uF  [0603]  (hidden comment: CGA3E2X7R1E104K080AA)
C133  ValueDisplayed: 330pF  [0603]  (hidden comment: 06035A331JAT2A)
C134  ValueDisplayed: 330pF  [0603]  (hidden comment: 06035A331JAT2A)
C135  Cap_F: 10nF  VDC_V: 100V  [0603]  (hidden comment: GRM188R72A103KA01D)
C139  Cap_F: 1nF  VDC_V: 250V  [0603]  (hidden comment: GRM188R72E102KW07D)
C140  ValueDisplayed: 3900pF  VDC_V: 100V  [0603]  (hidden comment: C1608C0G2A392J080AE)
C141  ValueDisplayed: 0.1uF  [0603]  (hidden comment: CGA3E2X7R1E104K080AA)
C142  Cap_F: 2.2µF  VDC_V: 16V  [0603]  (hidden comment: CC0603KRX7R7BB225)
C143  Cap_F: 2.2µF  [0603]  (hidden comment: CC0603KRX7R7BB225)
C144  ValueDisplayed: 0.1uF  [0603]  (hidden comment: CGA3E2X7R1E104K080AA)
C146  Cap_F: 100nF  [FP-CL10B104KA8VPJC_0603-MFG]  (hidden comment: CL10B104KA8VPJC)
C147  Cap_F: 100nF  [0603]  (hidden comment: 06033C104KAT2A)
C148  Cap_F: 1µF  [FP-CL10B105KA8VPJC_0603-MFG]  (hidden comment: CL10B105KA8VPJC)
C151  Cap_F: 100nF  [FP-CL10B104KA8VPJC_0603-MFG]  (hidden comment: CL10B104KA8VPJC)
C152  VDC_V: 25V  ValueDisplayed: 0.01uF  [0603]  (hidden comment: C0603H103J3GACTU)
C153  ValueDisplayed: 3900pF  VDC_V: 100V  [0603]  (hidden comment: C1608C0G2A392J080AE)
C193  ValueDisplayed: 3300pF  [0603]  (hidden comment: GRM1885C1H332JA01D)
C194  ValueDisplayed: 330pF  [0603]  (hidden comment: 06035A331JAT2A)
C195  ValueDisplayed: 330pF  [0603]  (hidden comment: 06035A331JAT2A)
C272  0603ZC100KAT2A  [0603]  (value not drawn)
C273  0603ZC100KAT2A  [0603]  (value not drawn)
C315  ValueDisplayed: 330pF  [0603]  (hidden comment: 06035A331JAT2A)
C316  ValueDisplayed: 330pF  [0603]  (hidden comment: 06035A331JAT2A)
C317  ValueDisplayed: 330pF  [0603]  (hidden comment: 06035A331JAT2A)
C318  ValueDisplayed: 330pF  [0603]  (hidden comment: 06035A331JAT2A)
C324  ValueDisplayed: 3900pF  VDC_V: 100V  [0603]  (hidden comment: C1608C0G2A392J080AE)
C334  ValueDisplayed: 3900pF  VDC_V: 100V  [0603]  (hidden comment: C1608C0G2A392J080AE)
D12  value Green  [WL-SMCW_GREEN]  (hidden comment: 150060VS75000)
L13  74279228260  [0603]  (value not drawn)
L14  74279228260  [0603]  (value not drawn)
L15  74279228260  [0603]  (value not drawn)
L17  74279228260  [0603]  (value not drawn)
L18  74279228260  [0603]  (value not drawn)
R14  ValueDisplayed: 220  [0603]  (hidden comment: CRCW0603220RJNEA)
R36  ValueDisplayed: 0  [0603]  (hidden comment: RMCF0603ZT0R00)
R45  ValueDisplayed: 8.2k  [0603]  (hidden comment: RC0603JR-078K2L)
R46  ValueDisplayed: 1.2k  [0603]  (hidden comment: RC0603JR-071K2L)
R61  ValueDisplayed: 0  [0603]  (hidden comment: RMCF0603ZT0R00)
R63  ValueDisplayed: 0  [0603]  (hidden comment: RMCF0603ZT0R00)
R112  ValueDisplayed: 634k  [0805_HV1]  (hidden comment: RT0805BRD07634KL)
R124  ValueDisplayed: 634k  [0805_HV1]  (hidden comment: RT0805BRD07634KL)
R129  ValueDisplayed: 160  [1210]  (hidden comment: RC1210JR-07160RL)
R131  ValueDisplayed: 100k  [0603]  (hidden comment: CRCW0603100KJNEAC)
R135  ValueDisplayed: 8.06k  [0603]  (hidden comment: RT0603DRE079K2L)
R136  ValueDisplayed: 10.0  [0603]  (hidden comment: TNPW060310R0BEEA)
R137  ValueDisplayed: 0  [0603]  (hidden comment: RMCF0603ZT0R00)
R138  ValueDisplayed: 10.0k  [TNPW0603]  (hidden comment: TNPW060310K0BEEA)
R139  ValueDisplayed: 68.1  [0603]  (hidden comment: CRCW060368R1FKEA)
R140  ValueDisplayed: 10.0  [0603]  (hidden comment: TNPW060310R0BEEA)
R141  ValueDisplayed: 0  [0603]  (hidden comment: RMCF0603ZT0R00)
R142  ValueDisplayed: 10.0k  [TNPW0603]  (hidden comment: TNPW060310K0BEEA)
R143  ValueDisplayed: 8.06k  [0603]  (hidden comment: RT0603DRE079K2L)
R145  ValueDisplayed: 634k  [0805_HV1]  (hidden comment: RT0805BRD07634KL)
R146  ValueDisplayed: 634k  [0805_HV1]  (hidden comment: RT0805BRD07634KL)
R148  ValueDisplayed: 634k  [0805_HV1]  (hidden comment: RT0805BRD07634KL)
R149  ValueDisplayed: 634k  [0805_HV1]  (hidden comment: RT0805BRD07634KL)
R151  ValueDisplayed: 634k  [0805_HV1]  (hidden comment: RT0805BRD07634KL)
R152  ValueDisplayed: 634k  [0805_HV1]  (hidden comment: RT0805BRD07634KL)
R153  ValueDisplayed: 8.06k  [0603]  (hidden comment: RT0603DRE079K2L)
R156  ValueDisplayed: 10.0k  [TNPW0603]  (hidden comment: TNPW060310K0BEEA)
R157  ValueDisplayed: 68.1  [0603]  (hidden comment: CRCW060368R1FKEA)
R158  ValueDisplayed: 10.0k  [0603]  (hidden comment: RT0603BRD0710KL)
R159  ValueDisplayed: 10.0k  [TNPW0603]  (hidden comment: TNPW060310K0BEEA)
R160  ValueDisplayed: 8.06k  [0603]  (hidden comment: RT0603DRE079K2L)
R163  ValueDisplayed: 10.0k  [0603]  (hidden comment: RG1608P-103-B-T5)
R164  ValueDisplayed: 10.0k  [0603]  (hidden comment: CRCW06030000Z0EA)
R166  ValueDisplayed: 68.1  [0603]  (hidden comment: CRCW060368R1FKEA)
R167  ValueDisplayed: 51  [0603]  (hidden comment: CRCW060351R0JNEA)
R168  ValueDisplayed: 68.1  [0603]  (hidden comment: CRCW060368R1FKEA)
R169  ValueDisplayed: 10.0k  [0603]  (hidden comment: RG1608P-103-B-T5)
TP8  5015  [Testpoint_Keystone_Miniature]
TP9  5015  [Testpoint_Keystone_Miniature]
TP18  5015  [Testpoint_Keystone_Miniature]
TP19  5015  [Testpoint_Keystone_Miniature]
TP31  5015  [Testpoint_Keystone_Miniature]
U11  OPA2320AIDRGT  [DRG0008A]  (parts A,B of 2)
U15  TMCS1133B1QDVGR  [DVG0010A-MFG]
U16  TLV76050DBZR  [DBZ0003A_N]
U18  AMC1302QDWVRQ1  [DWV0008A]
U21  AMC1311BDWVR  [DWV0008A]
U25  OPA320AIDBVR  [DBV0005A_N]

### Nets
1V65_1: C135.1 C152.1 C316.2 C318.2 R143.1 R160.1 R166.2 ; off-sheet 1.65V_1S  [also labelled 1.65V_1S]
3V3_A: C146.1 C147.1 C148.2 L14.2 L15.1 L18.2 R45.1 R163.1 U15.9(VS) U15.10(VS) U25.5(V+)
3V3_D: R164.2
5V_ISO_P: C117.2 C118.1 L13.2 L17.2 U16.1(OUT)
+15V_BOT1: R129.1
-4V_BOT1: C119.2 C120.1 R14.2 R131.1
GND: C126.1 C128.2 C131.2 C132.2 C133.2 C134.2 C135.2 C140.1 C141.2 C142.2 C146.2 C147.2 C148.1 C151.2 C152.2 C153.2 C194.2 C195.2 C324.1 C334.2 R46.2 R169.2 TP31.1 U11.4(V-) U11.9(EP) U15.3(GND) U18.5(GND2) U21.5(GND2) U25.2(V-)
GND_BOT1: C115.2 C116.1 C117.1 C118.2 C119.1 C120.2 C123.1 C127.2 C129.2 C130.2 C143.2 C144.2 C272.2 C273.2 D12.2(A) R36.2 R131.2 U16.3(GND) U18.4(GND1)
PGND: C139.2 C273.1 R36.1 R158.1 U21.3(SHTDN) U21.4(GND1)
VCC_OPA: C126.2 L15.2 U11.8(V+)
~{FLT_PRI}: C324.2 R164.1 R167.2 ; off-sheet ~{FLT_PRI}
I_DC_PRI: C128.1 R139.2 TP8.1 ; off-sheet I_DC_PRI
I_PRI_N: U15.1(IN+) ; off-sheet I_PRI_N  [project net D2L_P]
I_PRI_P: U15.2(IN-) ; off-sheet I_PRI_P
I_TANK_PRI: C153.1 R168.2 TP19.1 ; off-sheet I_TANK_PRI
Iin+: R136.1 ; off-sheet Iin+
Iin-: R140.1 ; off-sheet Iin-
V_DC_PRI: C140.2 R157.2 TP9.1 ; off-sheet V_DC_PRI
VBUS_P: R112.1 ; off-sheet VBUS_P  [project net D1H_P]
NetC115_1: C115.1 C116.2 R129.2 U16.2(IN)
NetC123_2: C123.2 C124.1 R136.2 U18.2(VINP)
NetC124_2: C124.2 C127.1 R140.2 U18.3(VINN)
NetC125_1: C125.1 C134.1 R137.2 R142.2
NetC125_2: C125.2 C133.1 R138.2 R141.2
NetC129_1: C129.1 C130.1 L13.1 U18.1(VDD1)
NetC131_1: C131.1 C132.1 L14.1 U18.8(VDD2)
NetC139_1: C139.1 C272.1 R152.1 R158.2 U21.2(VINP)
NetC141_1: C141.1 C142.1 L18.1 U21.8(VDD2)
NetC143_1: C143.1 C144.1 L17.1 U21.1(VDD1)
NetC151_1: C151.1 R163.2 R169.1 U25.3(IN+)
NetC193_1: C193.1 C195.1 R61.2 R159.2
NetC193_2: C193.2 C194.1 R63.2 R156.2
NetC315_1: C315.1 R135.1 R138.1 U11.2(IN_A-)
NetC315_2: C315.2 R135.2 R139.1 U11.1(OUT_A)
NetC316_1: C316.1 R142.1 R143.2 U11.3(IN_A+)
NetC317_1: C317.1 R153.1 R156.1 U11.6(IN_B-)
NetC317_2: C317.2 R153.2 R157.1 U11.7(OUT_B)
NetC318_1: C318.1 R159.1 R160.2 U11.5(IN_B+)
NetC334_1: C334.1 R45.2 R46.1 U15.8(VOC)
NetD12_1: D12.1(K) R14.1
NetR61_1: R61.1 U21.7(VOUTP)
NetR63_1: R63.1 U21.6(VOUTN)
NetR112_2: R112.2 R124.2
NetR124_1: R124.1 R145.2
NetR137_1: R137.1 U18.7(VOUTP)
NetR141_1: R141.1 U18.6(VOUTN)
NetR145_1: R145.1 R146.2
NetR146_1: R146.1 R148.1
NetR148_2: R148.2 R149.2
NetR149_1: R149.1 R151.2
NetR151_1: R151.1 R152.2
NetR166_1: R166.1 U25.1(OUT) U25.4(IN-)
NetR167_1: R167.1 TP18.1 U15.7(~{OC})
NetR168_1: R168.1 U15.6(VOUT)

Not connected (* = marked no-connect by the designer): U15 4(~{FAULT})* 5(NC)*

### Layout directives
net class HV_P_N: 5V_ISO_P, +15V_BOT1, -4V_BOT1, GND_BOT1, Iin+, Iin-, PGND, VBUS_P
net class HV_P_SW2: D2L_P, I_PRI_P
net class HV: VBUS_P

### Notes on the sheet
- Primary Side Current Sensing
- Primary Side Voltage Sensing
- Primary Side Tank Current Sensing
- 1V65 Generation
- OC Setting to 45A
- Pin 14 and pin 16 needs to be swapped for TMCS1133

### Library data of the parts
C115 C118 C119 C148 = CMP-0121052-1: Cap Ceramic 1uF 25V X7R ±10% Pad SMD 0603 +125°C T/R; Manufacturer: Samsung; AEC Grade: Grade 1; AEC Qualified: Yes; SizeZ_mm: 0.9mm; TempCo: 15%; Value: 1µF
C116 C120 = CMP-0006356-2: CAP, CERM, 0.1 uF, 50 V, +/- 10%, X7R, AEC-Q200 Grade 1, 0402; Manufacturer: MuRata; TaMin_C: -55°C; Polarized: N; SizeAreaWB_mm2: 3; Value1: Unknown; U/M: EA; Value: 0.1uF; TaMax_C: 125°C; SizeZ_mm: 0.6; SizeX_mm: 1; SizeY_mm: 0.5; Cap_Case: 0402; AEC Qualified: Y; Cap_F: 100nF; AEC Category: Q200
C117 = CMP-0006356-2: CAP, CERM, 0.1 uF, 50 V, +/- 10%, X7R, AEC-Q200 Grade 1, 0402; Manufacturer: MuRata; TaMin_C: -55°C; Polarized: N; SizeAreaWB_mm2: 3; Value1: Unknown; U/M: EA; Value: 0.1uF; TaMax_C: 125°C; SizeZ_mm: 0.6; SizeX_mm: 1; SizeY_mm: 0.5; Cap_Case: 0402; Value2: 50V; AEC Qualified: Y; Cap_F: 100nF; AEC Category: Q200
C123 C127 C272 C273 = CMP-0006811-4: CAP, CERM, 10 pF, 10 V, +/- 10%, X7R, 0603; Manufacturer: AVX; TaMin_C: -55°C; Polarized: N; SizeAreaWB_mm2: 4.68; Value1: Unknown; U/M: EA; Value: 10pF; TaMax_C: 125°C; SizeZ_mm: 1; SizeX_mm: 1.6; SizeY_mm: 0.8; Value2: 10V; SizeArea_mm2: 1.28; AEC Category: Q200
C124 = CMP-0006810-4: CAP, CERM, 0.082 uF, 16 V, +/- 10%, X7R, 0603; Manufacturer: AVX; TaMin_C: -55°C; ESR_ohm: 42m; Polarized: N; SizeAreaWB_mm2: 4.68; Value1: 0.042 ohm; U/M: EA; TaMax_C: 125°C; SizeZ_mm: 1; SizeX_mm: 1.6; SizeY_mm: 0.8; SizeArea_mm2: 1.28; AEC Category: Q200
C125 C193 = CMP-0007210-4: CAP, CERM, 3300 pF, 50 V, +/- 5%, C0G/NP0, 0603; Manufacturer: MuRata; TaMin_C: -55°C; Polarized: N; SizeAreaWB_mm2: 4.68; Value1: Unknown; U/M: EA; Value: 3300pF; TaMax_C: 125°C; SizeZ_mm: 1; SizeX_mm: 1.6; SizeY_mm: 0.8; Value2: 50V; SizeArea_mm2: 1.28; Cap_F: 3.3nF; AEC Category: Q200
C126 C146 C151 = CMP-0121051-1: Automotive CAP, 100㎋, 25V, ±10%, X7R, 0603, 5mm Bending; Manufacturer: Samsung; AEC Grade: Grade 1; AEC Qualified: Yes; SizeZ_mm: 0.9mm; TempCo: 15%; Value: 100nF
C128 C139 = CMP-0007490-4: CAP, CERM, 1000 pF, 250 V, +/- 10%, X7R, 0603; Manufacturer: MuRata; TaMin_C: -55°C; Polarized: N; SizeAreaWB_mm2: 4.68; Value1: Unknown; U/M: EA; Value: 1000pF; TaMax_C: 125°C; SizeZ_mm: 1; SizeX_mm: 1.6; SizeY_mm: 0.8; SizeArea_mm2: 1.28; AEC Category: Q200
C129 C131 C142 = CMP-0079605-1: CAP, CERM, 2.2 µF, 16 V,+/- 10%, X7R, 0603; Manufacturer: Yageo America; TaMin_C: -55°C; Polarized: N; SizeAreaWB_mm2: 4.68; U/M: EA; Value: 2.2uF; TaMax_C: 125°C; SizeZ_mm: 1; SizeX_mm: 1.6; SizeY_mm: 0.8; SizeArea_mm2: 1.28; AEC Category: Q200
C130 C132 C141 C144 = CMP-0007077-5: CAP, CERM, 0.1 uF, 25 V, +/- 10%, X7R, AEC-Q200 Grade 1, 0603; Manufacturer: TDK; TaMin_C: -55°C; Polarized: N; SizeAreaWB_mm2: 4.68; Value1: Unknown; U/M: EA; Value: 0.1uF; TaMax_C: 125°C; SizeZ_mm: 1; SizeX_mm: 1.6; SizeY_mm: 0.8; Value2: 25V; SizeArea_mm2: 1.28; CompType: Capacitor; AEC Qualified: Y; Cap_F: 100nF; AEC Category: Q200
C133 C134 C194 C195 C315-C318 = CMP-0006784-4: CAP, CERM, 330 pF, 50 V, +/- 5%, C0G/NP0, 0603; Manufacturer: AVX; TaMin_C: -55°C; ESR_ohm: 0.071; Polarized: N; SizeAreaWB_mm2: 4.68; Value1: 0.071 ohm; U/M: EA; Value: 330pF; TaMax_C: 125°C; SizeZ_mm: 1; SizeX_mm: 1.6; SizeY_mm: 0.8; Value2: 50V; SizeArea_mm2: 1.28; AEC Category: Q200
C135 = CMP-0007468-5: CAP, CERM, 0.01 uF, 100 V, +/- 10%, X7R, 0603; Manufacturer: MuRata; TaMin_C: -55°C; Polarized: N; SizeAreaWB_mm2: 4.68; Value1: Unknown; U/M: EA; Value: 0.01uF; TaMax_C: 125°C; SizeZ_mm: 1; SizeX_mm: 1.6; SizeY_mm: 0.8; SizeArea_mm2: 1.28; AEC Category: Q200
C140 C153 C324 C334 = CMP-0860987-1: CAP, CERM, 3900 pF, 100 V,+/- 5%, C0G/NP0, 0603; Manufacturer: TDK; SizeArea_mm2: 1.28; SizeY_mm: 0.8; AEC Qualified: N; Cap_F: 3.9nF; Value: 3900pF; U/M: EA; AEC Category: Q200; SizeZ_mm: 1; TaMin_C: -55°C; TaMax_C: 125°C; SizeAreaWB_mm2: 4.68; SizeX_mm: 1.6
C143 = CMP-0079605-1: CAP, CERM, 2.2 µF, 16 V,+/- 10%, X7R, 0603; Manufacturer: Yageo America; TaMin_C: -55°C; Polarized: N; SizeAreaWB_mm2: 4.68; U/M: EA; Value: 2.2uF; TaMax_C: 125°C; SizeZ_mm: 1; SizeX_mm: 1.6; SizeY_mm: 0.8; Value2: 16V; SizeArea_mm2: 1.28; AEC Category: Q200
C147 = CMP-0006753-4: CAP, CERM, 0.1 uF, 25 V, +/- 10%, X7R, 0603; Manufacturer: AVX; TaMin_C: -55°C; ESR_ohm: 0.05; Polarized: N; SizeAreaWB_mm2: 4.68; Value1: 0.05 ohm; U/M: EA; Value: 0.1uF; TaMax_C: 125°C; SizeZ_mm: 1; SizeX_mm: 1.6; SizeY_mm: 0.8; Value2: 25V; SizeArea_mm2: 1.28; AEC Category: Q200
C152 = CMP-0006975-4: CAP, CERM, 0.01 uF, 25 V, +/- 5%, C0G/NP0, 0603; Manufacturer: Kemet; TaMin_C: -55°C; Polarized: N; SizeAreaWB_mm2: 4.68; Value1: Unknown; U/M: EA; Value: 0.01uF; TaMax_C: 200°C; SizeZ_mm: 1; SizeX_mm: 1.6; SizeY_mm: 0.8; SizeArea_mm2: 1.28; Cap_F: 10nF; AEC Category: Q200
D12 = CMP-0002894-2: LED, Green, SMD; Manufacturer: Wurth Elektronik; Type: AlInGaP; Value2: 2V; Io_A: 20mA; Value1: W
L13-L15 L17 L18 = CMP-0003155-2: Ferrite Bead, 26 ohm @ 100 MHz, 6.5 A, 0603; Manufacturer: Wurth Elektronik; Ztyp@1GHz_Ohm: 35.506; ZTyp@100MHz_Ohm: 26; SizeAreaWB_mm2: 4.68; DCR_ohm: 5m; Value1: 0.005 ohm; Value: 26 ohm; Imax_A: 6.5A; SizeZ_mm: 1; SizeX_mm: 1.6; SizeY_mm: 0.8; SizeArea_mm2: 1.28
R14 = CMP-0025756-4: RES, 220, 5%, 0.1 W, AEC-Q200 Grade 0, 0603; Manufacturer: Vishay-Dale; Power_W: 100mW; TempCo: 200 ppm/C; Value_Code: 220R; Value: 220; EIA_Code: E24; SizeX_mm: 1.6; SizeY_mm: 0.8; SizeZ_mm: 1; Value2: 0.1W; SizeArea_mm2: 1.28; AEC Qualified: Y; VDC_V: 75V; AEC Category: Q200; AEC Grade: 0
R36 R61 R63 R137 R141 = CMP-0023343-3: RES, 0, 1%, 0.1 W, AEC-Q200 Grade 0, 0603; Manufacturer: Stackpole Electronics Inc; Power_W: 100mW; TempCo: ppm/C; U/M: EA; Value: 0; SizeX_mm: 1.6; SizeY_mm: 0.8; SizeZ_mm: 1; Value2: 0.1W; SizeArea_mm2: 1.28; CompType: Resistor; AEC Qualified: Y; AEC Category: Q200
R45 = CMP-0025942-5: RES, 8.2 k, 5%, 0.1 W, 0603; Manufacturer: Yageo; Power_W: 100mW; TempCo: 100 ppm/C; Value_Code: 8k20; Value: 8.2k; EIA_Code: E24; SizeX_mm: 1.6; SizeY_mm: 0.8; SizeZ_mm: 1; Value2: 0.1W; SizeArea_mm2: 1.28; AEC Qualified: N; VDC_V: 75V; AEC Category: Q200; SizeAreaWB_mm2: 4.68
R46 = CMP-0025894-5: RES, 1.2 k, 5%, 0.1 W, 0603; Manufacturer: Yageo; Power_W: 100mW; TempCo: 100 ppm/C; Value_Code: 1k20; Value: 1.2k; EIA_Code: E24; SizeX_mm: 1.6; SizeY_mm: 0.8; SizeZ_mm: 1; Value2: 0.1W; SizeArea_mm2: 1.28; AEC Qualified: N; VDC_V: 75V; AEC Category: Q200; SizeAreaWB_mm2: 4.68
R112 R124 R145 R146 R148 R149 R151 R152 = CMP-0020237-2: RES, 634 k, 0.1%, 0.125 W, 0805; Manufacturer: Yageo America; Power_W: 125mW; TempCo: 25 ppm/C; U/M: EA; Value: 634k; EIA_Code: E192; SizeX_mm: 2; SizeY_mm: 1.25; SizeZ_mm: 1.45; Value2: 0.125W; SizeArea_mm2: 2.5; VDC_V: 150V; AEC Category: Q200
R129 = CMP-0083464-1: RES, 160, 5%, 0.5 W, 1210; Manufacturer: Yageo; Power_W: 500mW; TempCo: 100 ppm/C; SizeAreaWB_mm2: 14.7; Value_Code: 160R; Value: 160; EIA_Code: E24; SizeX_mm: 3.2; SizeY_mm: 2.5; SizeZ_mm: 1.35; Value2: 0.5W; SizeArea_mm2: 8; AEC Qualified: N; VDC_V: 200V; AEC Category: Q200
R131 = CMP-0082530-1: RES, 100 k, 5%, 0.1 W, 0603; Manufacturer: Vishay-Dale; Power_W: 100mW; TempCo: 200 ppm/C; SizeAreaWB_mm2: 4.68; Value: 100k; EIA_Code: E24; SizeX_mm: 1.6; SizeY_mm: 0.8; SizeZ_mm: 1; Value2: 0.1W; SizeArea_mm2: 1.28; AEC Qualified: N; VDC_V: 75V; AEC Category: Q200
R135 R143 R153 R160 = CMP-0023603-3: RES, 8.06 k, 0.1%, 0.1 W, 0603; Manufacturer: Susumu Co Ltd; PartNumber: RG1608P-8061-B-T5; Power_W: 100mW; TempCo: 25 ppm/C; Value_Code: 8k06; U/M: EA; Value: 8.06k; EIA_Code: E192; SizeX_mm: 1.6; SizeY_mm: 0.8; SizeZ_mm: 1; Value2: 0.1W; SizeArea_mm2: 1.28; VDC_V: 75V; AEC Category: Q200
R136 R140 = CMP-0025687-2: RES, 10.0, 0.1%, 0.1 W, 0603; Manufacturer: Vishay-Dale; Power_W: 100mW; TempCo: 25 ppm/C; Value_Code: 10R0; U/M: EA; Value: 10.0; EIA_Code: E192; Res_ohm: 10; SizeX_mm: 1.6; SizeY_mm: 0.8; SizeZ_mm: 1; Value2: 0.1W; SizeArea_mm2: 1.28; VDC_V: 75V; AEC Category: Q200
R138 R142 R156 R159 = CMP-0025686-1: RES, 10.0 k, 0.1%, 0.1 W, AEC-Q200 Grade 1, 0603; Manufacturer: Vishay-Dale; Power_W: 100mW; TempCo: 25 ppm/C; Value_Code: 10k0; U/M: EA; Value: 10.0k; EIA_Code: E192; Res_ohm: 10k; SizeX_mm: 1.6; SizeY_mm: 0.85; SizeZ_mm: 0.55; Value2: 0.1W; SizeArea_mm2: 1.36; CompType: Resistor; AEC Qualified: Y; VDC_V: 75V; AEC Grade: 1; AEC Category: Q200
R139 R157 R166 R168 = CMP-0022553-4: RES, 68.1, 1%, 0.1 W, AEC-Q200 Grade 0, 0603; Manufacturer: Vishay-Dale; Value: 68.1; Value_Code: 68R1; Power_W: 100mW; Value2: 0.1W; VDC_V: 75V; TempCo: 100 ppm/C; SizeArea_mm2: 1.28; SizeX_mm: 1.6; SizeY_mm: 0.8; SizeZ_mm: 1; EIA_Code: E96; AEC Category: Q200; AEC Qualified: Y; AEC Grade: 0
R158 = CMP-0023653-3: RES, 10.0 k, 0.1%, 0.1 W, 0603; Manufacturer: Yageo America; Power_W: 100mW; TempCo: 25 ppm/C; Value_Code: 10k0; U/M: EA; Value: 10.0k; EIA_Code: E192; Res_ohm: 10k; SizeX_mm: 1.6; SizeY_mm: 0.8; SizeZ_mm: 1; Value2: 0.1W; SizeArea_mm2: 1.28; VDC_V: 75V; AEC Category: Q200
R163 R169 = CMP-0023404-3: RES, 10.0 k, 0.1%, 0.1 W, 0603; Manufacturer: Susumu Co Ltd; Value: 10.0k; Res_ohm: 10k; Value_Code: 10k0; Power_W: 100mW; Value2: 0.1W; VDC_V: 75V; TempCo: 25 ppm/C; SizeArea_mm2: 1.28; SizeX_mm: 1.6; SizeY_mm: 0.8; SizeZ_mm: 1; EIA_Code: E192; U/M: EA; AEC Category: Q200
R164 = CMP-0023337-3: RES, 10.0 k, 1%, 0.1 W, 0603; Manufacturer: Vishay Draloric; PartNumber: RCG060310K0FKEA; Power_W: 100mW; TempCo: 100 ppm/C; Value_Code: 10k0; U/M: EA; Value: 10.0k; EIA_Code: E96; Res_ohm: 10k; SizeX_mm: 1.6; SizeY_mm: 0.8; SizeZ_mm: 1; Value2: 0.1W; SizeArea_mm2: 1.28; AEC Qualified: N; VDC_V: 75V; AEC Category: Q200
R167 = CMP-0025825-4: RES, 51, 5%, 0.1 W, AEC-Q200 Grade 0, 0603; Manufacturer: Vishay-Dale; Power_W: 100mW; TempCo: 200 ppm/C; Value_Code: 51R0; Value: 51; EIA_Code: E24; SizeX_mm: 1.6; SizeY_mm: 0.8; SizeZ_mm: 1; Value2: 0.1W; SizeArea_mm2: 1.28; AEC Qualified: Y; VDC_V: 75V; AEC Category: Q200; AEC Grade: 0
TP8 TP9 TP18 TP19 TP31 = CMP-0055152-2: Test Point, Miniature, SMT; Manufacturer: Keystone Electronics; CT: TRUE; Green_Lifecycle: Active; Green_REACh: Passed; CNHeader: FALSE
U11 = CMP-0040683-2: Precision, 20 MHz, 0.9 pA Ib, RRIO, CMOS Operational Amplifier, 1.8 to 5.5 V, -40 to 125 degC, 8-pin SON (DRG8), Green (RoHS & no Sb/Br); Manufacturer: Texas Instruments; Sub Family: High Output Current Amplifier (>=50mA), Low Input Bias Current Amp (<=10pA), Low Noise Amp (<=10nV/rtHz), Low Offset Voltage Amplifier (<=500uV), Low Supply Voltage Amplifier (<=2.7V), Precision Amplifier; Total Supply Voltage(Min)(+5V is 5, +/-5V is 10): 1.8; Slew Rate(Typ)(V/us): 10; Vio (25C)(Max)(mV): 0.15; Total Supply Voltage(Max)(+5V is 5, +/-5V is 10): 5.5; IIB(Max)(pA): 400; Offset Drift(Typ)(uV/C): 1.5; Iq per channel(Max)(mA): 1.6; CMRR(Min)(dB): 100; Number of Channels: 2; Vn at 1kHz(Typ)(nV/rtHz): 8.5
U15 = CMP-0097984-1: Manufacturer: Texas Instruments; Standoff Height: 0.1mm; SizeZ_mm: 2.65mm
U16 = CMP-0074892-1: 100-mA, 30-V, Fixed-Output, Linear-Voltage Regulator, DBZ0003A (SOT-23-3); Alternate PartNumber: TLV76050DBZT; Alternate Manufacturer: Texas Instruments; SizeAreaWB_mm2: 14.0; SizeZ_mm: 1.12; SizeX_mm: 2.5; SizeY_mm: 3.0; SizeArea_mm2: 7.5; CompType: IC; AEC Qualified: N; AEC Category: Q200
U18 = CMP-0080587-1: Precision Reinforced Isolated Amplifier for Current Sensing, DWV0008A (SOIC-8); Alternate Manufacturer: Texas Instruments; SizeAreaWB_mm2: 105.975; SizeZ_mm: 2.8; SizeX_mm: 11.5; SizeY_mm: 5.85; SizeArea_mm2: 67.275; CompType: IC; AEC Qualified: Y; AEC Category: Q200
U21 = CMP-0078341-1: Precision, 2-V Input, Reinforced Isolated Amplifier, DWV0008A (SOIC-8); Alternate Manufacturer: Texas Instruments; SizeAreaWB_mm2: 105.975; SizeZ_mm: 2.8; SizeX_mm: 11.5; SizeY_mm: 5.85; SizeArea_mm2: 67.275; CompType: IC; AEC Qualified: N; AEC Category: Q200
U25 = CMP-0040888-1: Precision, 20 MHz, 0.9 pA Ib, RRIO, CMOS Operational Amplifier, 1.8 to 5.5 V, -40 to 125 degC, 5-pin SOT23 (DBV5), Green (RoHS & no Sb/Br); Manufacturer: Texas Instruments; CMRR(Min)(dB): 100; Iq per channel(Max)(mA): 1.75; IIB(Max)(pA): 0.9; Total Supply Voltage(Min)(+5V is 5, +/-5V is 10): 1.8; Sub Family: High Output Current Amplifier (>=50mA), Low Input Bias Current Amp (<=10pA), Low Noise Amp (<=10nV/rtHz), Low Offset Voltage Amplifier (<=500uV), Low Supply Voltage Amplifier (<=2.7V), Precision Amplifier; Number of Channels: 2; Total Supply Voltage(Max)(+5V is 5, +/-5V is 10): 5.5; Offset Drift(Typ)(uV/C): 1.5; Vn at 1kHz(Typ)(nV/rtHz): 8.5; Slew Rate(Typ)(V/us): 10; Vio (25C)(Max)(mV): 0.15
